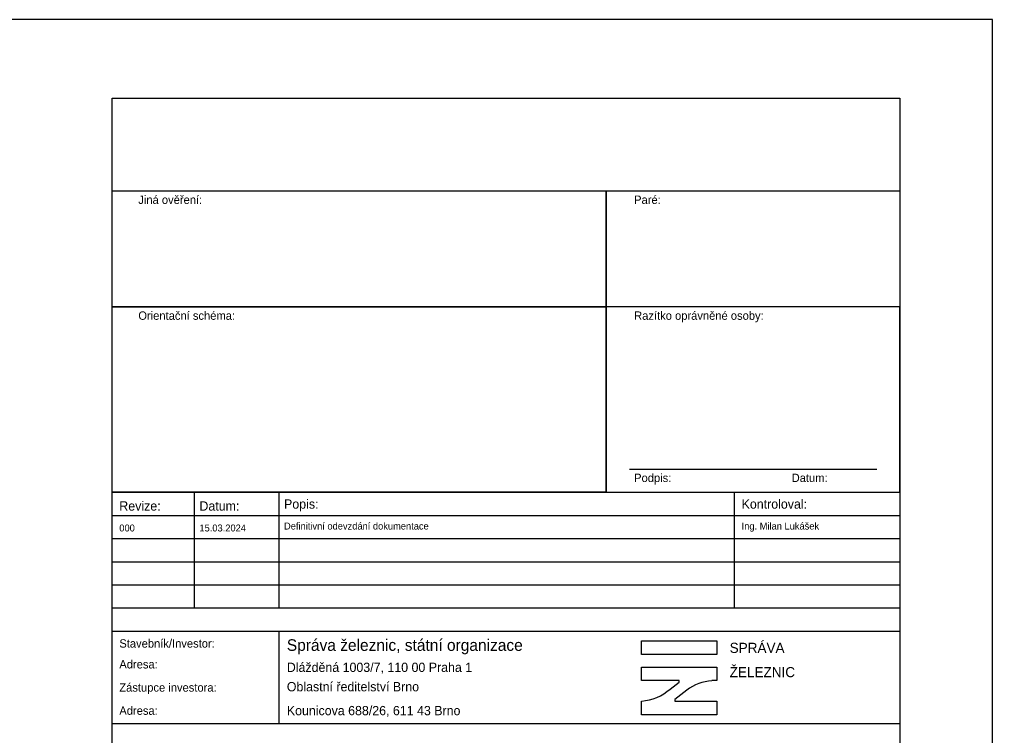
# Model space of a CAD drawing. Extents: x -1210 to -790, y -790 to -493.
# Drawn here: x -1000 to -790, y -647.5 to -493 of the extents above; entities that cross this region are included whole.
import ezdxf

# ---------------------------------------------------------------- set-up
doc = ezdxf.new("R2010")
doc.units = 0
for name, color, linetype in [('Default', 7, 'Continuous'), ('Rozpiska_Logo', 7, 'Continuous'), ('Rozpiska_pola_3', 7, 'Continuous'), ('Rozpiska_pole_1', 7, 'Continuous'), ('Rozpiska_pole_2', 7, 'Continuous'), ('Rozpiska_pole_4', 7, 'Continuous'), ('Rozpiska_pole_5', 7, 'Continuous'), ('Rozpiska_pole_6', 7, 'Continuous'), ('Rámečky-tisk', 7, 'Continuous'), ('Vrstva 50', 7, 'Continuous')]:
    doc.layers.add(name, color=color, linetype=linetype)

msp = doc.modelspace()

# ---------------------------------------------------------------- linework, layer by layer
at = {"layer": 'Default'}
msp.add_line((-873.35, -595), (-873.35, -530), dxfattribs=at)
at = {"layer": 'Rozpiska_Logo'}
for p, q in [((-859.6, -637.47), (-857.66, -636.01)), ((-857.66, -636.01), (-857.66, -635.66)), ((-855.97, -637.74), (-858.58, -639.76)), ((-858.58, -639.76), (-858.58, -640.07))]:
    msp.add_line(p, q, dxfattribs=at)
msp.add_lwpolyline([(-865.78, -627.09), (-849.48, -627.09), (-849.48, -630.02), (-865.78, -630.02)], close=True, dxfattribs=at)
for points in [[(-857.66, -635.66), (-865.78, -635.66), (-865.78, -632.73), (-849.48, -632.73), (-849.48, -635.66), (-850.56, -635.66)], [(-858.58, -640.07), (-849.48, -640.07), (-849.48, -643), (-865.78, -643), (-865.78, -640.07), (-865.72, -640.07)]]:
    msp.add_lwpolyline(points, dxfattribs=at)
for centre, radius, start, end in [((-849.82, -645.68), 10.04, 94.2142, 127.7808), ((-866.56, -629.58), 10.52, 274.6014, 311.4254)]:
    msp.add_arc(centre, radius, start, end, dxfattribs=at)
at = {"layer": 'Rozpiska_pola_3'}
msp.add_line((-868.35, -590), (-815, -590), dxfattribs=at)
at = {"layer": 'Rozpiska_pole_1'}
msp.add_lwpolyline([(-980, -510), (-810, -510), (-810, -775), (-980, -775)], close=True, dxfattribs=at)
at = {"layer": 'Rozpiska_pole_2'}
for points in [[(-980, -530), (-873.35, -530), (-873.35, -555), (-980, -555)], [(-873.35, -530), (-810, -530), (-810, -555), (-873.35, -555)], [(-980, -555), (-873.35, -555), (-873.35, -595), (-980, -595)], [(-810, -555), (-873.35, -555), (-873.35, -595), (-810, -595)]]:
    msp.add_lwpolyline(points, close=True, dxfattribs=at)
at = {"layer": 'Rozpiska_pole_4'}
for p, q in [((-962.23, -620), (-962.23, -595)), ((-943.95, -620), (-943.95, -595)), ((-845.7, -620), (-845.7, -595)), ((-980, -600), (-810, -600)), ((-980, -605), (-810, -605)), ((-980, -610), (-810, -610)), ((-980, -615), (-810, -615))]:
    msp.add_line(p, q, dxfattribs=at)
msp.add_lwpolyline([(-980, -595), (-810, -595), (-810, -620), (-980, -620)], close=True, dxfattribs=at)
at = {"layer": 'Rozpiska_pole_5'}
msp.add_line((-943.95, -645), (-943.95, -625), dxfattribs=at)
msp.add_lwpolyline([(-980, -625), (-810, -625), (-810, -645), (-980, -645)], close=True, dxfattribs=at)
at = {"layer": 'Rámečky-tisk'}
for p, q in [((-790, -493), (-1210, -493)), ((-790, -790), (-790, -493))]:
    msp.add_line(p, q, dxfattribs=at)
at = {"layer": 'Vrstva 50'}
msp.add_line((-790, -493), (-1210, -493), dxfattribs=at)
msp.add_lwpolyline([(-1210, -493), (-1210, -790), (-790, -790), (-790, -493)], dxfattribs=at)

# ---------------------------------------------------------------- texts
at = {"layer": 'Rozpiska_pola_3'}
for s, p in [('Paré:', (-867.35, -532.8)), ('Razítko oprávněné osoby:', (-867.35, -557.8)), ('Podpis:', (-867.35, -592.8)), ('Datum:', (-833.35, -592.8))]:
    msp.add_text(s, height=1.8, dxfattribs=at).set_placement(p)
at = {"layer": 'Rozpiska_pole_2'}
for s, p in [('Jiná ověření:', (-974.35, -532.8)), ('Orientační schéma:', (-974.35, -557.8))]:
    msp.add_text(s, height=1.8, dxfattribs=at).set_placement(p)
at = {"layer": 'Rozpiska_pole_4'}
for s, height, p in [('Revize:', 2, (-978.45, -598.97)), ('Datum:', 2, (-961.16, -598.97)), ('Popis:', 2, (-942.9, -598.55)), ('Kontroloval:', 2, (-844.15, -598.55)), ('000', 1.5, (-978.45, -603.47)), ('15.03.2024', 1.5, (-961.16, -603.47)), ('Definitivní odevzdání dokumentace', 1.5, (-942.9, -603.05)), ('Ing. Milan Lukášek', 1.5, (-844.15, -603.05))]:
    msp.add_text(s, height=height, dxfattribs=at).set_placement(p)
at = {"layer": 'Rozpiska_pole_5'}
for s, height, p in [('Stavebník/Investor:', 1.8, (-978.45, -628.53)), ('Správa železnic, státní organizace', 2.5, (-942.3, -629.23)), ('Adresa:', 1.8, (-978.45, -633.03)), ('Zástupce investora:', 1.8, (-978.45, -638.03)), ('Adresa:', 1.8, (-978.45, -643.03))]:
    msp.add_text(s, height=height, dxfattribs=at).set_placement(p)
at = {"layer": 'Rozpiska_pole_6'}
for s, height, p in [('SPRÁVA', 2.183, (-846.73, -629.67)), ('Dlážděná 1003/7, 110 00 Praha 1', 2, (-942.3, -633.78)), ('ŽELEZNIC', 2.183, (-846.73, -634.91)), ('Oblastní ředitelství Brno', 2, (-942.3, -637.96)), ('Kounicova 688/26, 611 43 Brno', 2, (-942.3, -643.12))]:
    msp.add_text(s, height=height, dxfattribs=at).set_placement(p)

doc.saveas('drawing.dxf')
